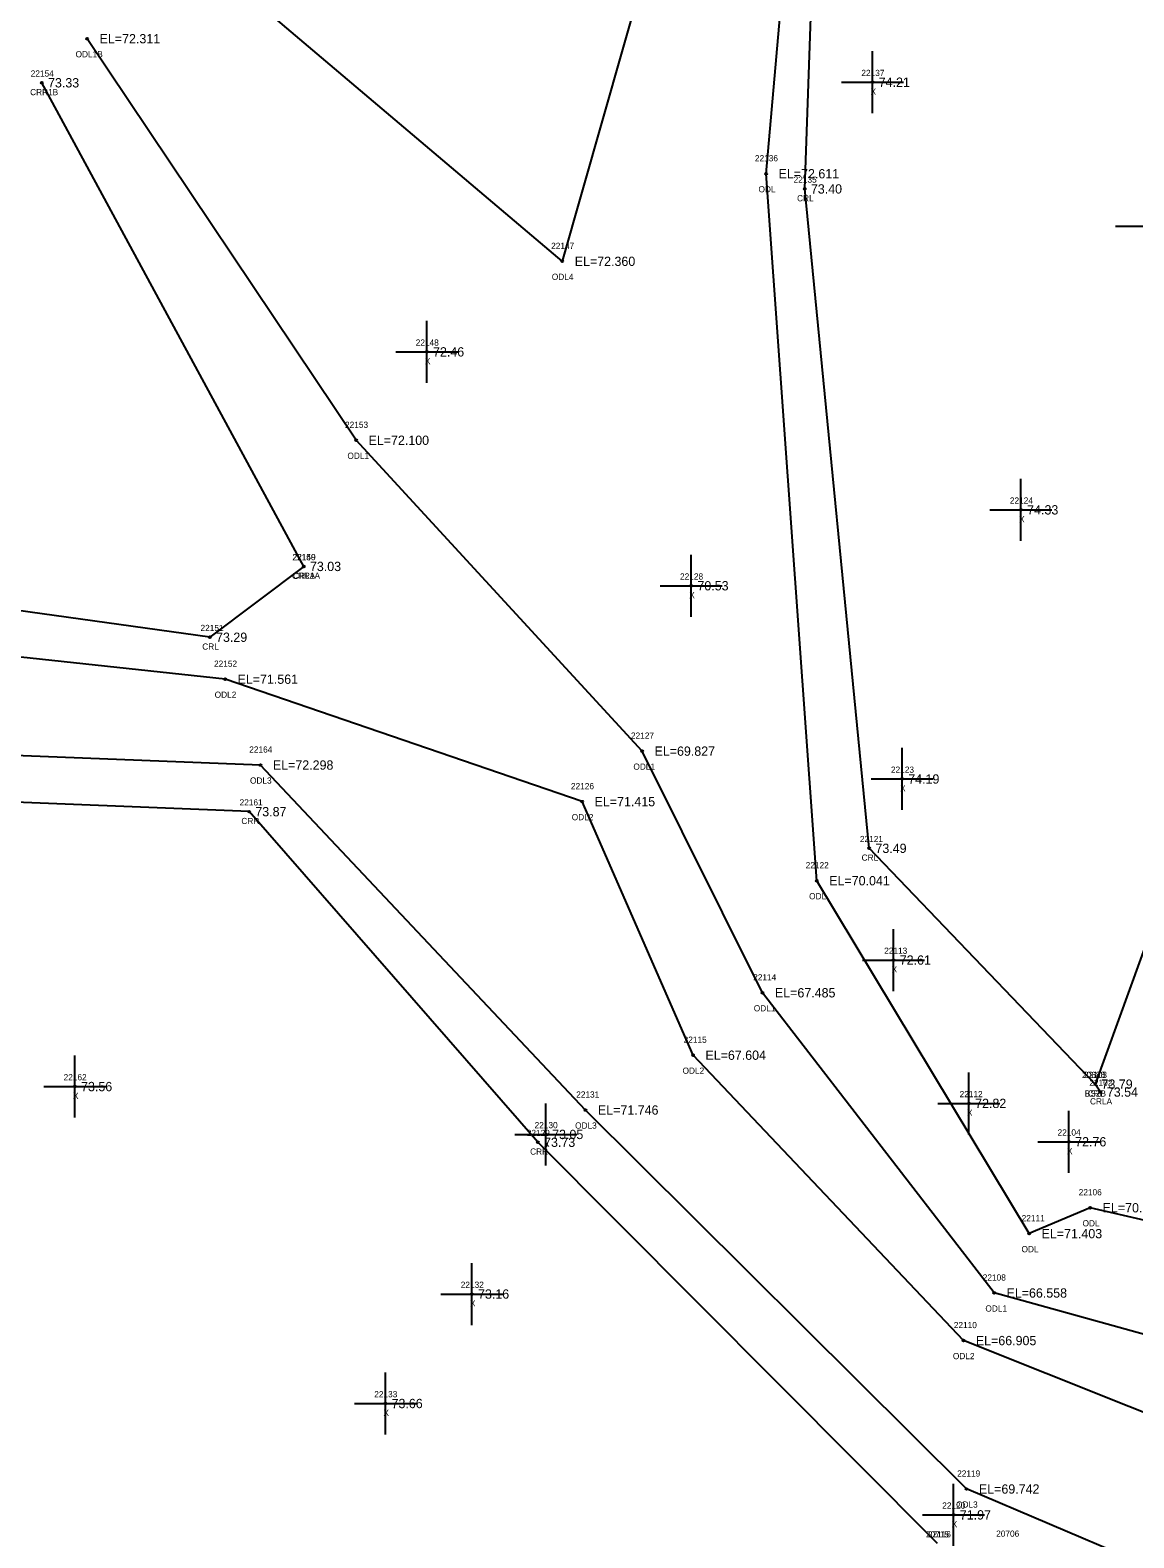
# Model space of a CAD drawing. Extents: x 2140110 to 2141565, y 506241 to 510327.
# Drawn here: x 2140519.7 to 2140697.7, y 508335.5 to 508578.6 of the extents above; entities that cross this region are included whole.
import ezdxf

# ---------------------------------------------------------------- set-up
doc = ezdxf.new("R2010")
doc.units = 0
for name, color, linetype in [('RD_DTM_BkLn2', 7, 'Continuous'), ('RD_DTM_BkLn_txCode', 7, 'Continuous'), ('RD_EX_H2O', 7, 'Continuous'), ('RD_EX_H2O_txCode', 7, 'Continuous'), ('RD_EX_Misc', 7, 'Continuous'), ('RD_EX_Misc_txCode', 7, 'Continuous'), ('RD_EX_Road_txCode', 7, 'Continuous'), ('RD_EX_TX_H2O_ELEV', 7, 'Continuous'), ('RD_EX_TX_Misc_ELEV', 7, 'Continuous'), ('RD_SMD_Locator', 7, 'Continuous')]:
    doc.layers.add(name, color=color, linetype=linetype)

msp = doc.modelspace()

# ---------------------------------------------------------------- linework, layer by layer
at = {"layer": 'RD_DTM_BkLn2'}
msp.add_lwpolyline([(2140933.17, 509059.34), (2140899.55, 508966.27), (2140862.01, 508865.36), (2140827.25, 508770.26), (2140789.14, 508668.2), (2140752.1, 508574.12), (2140728.15, 508510.71), (2140713.66, 508469.65), (2140691.53, 508408.63)], dxfattribs=at)
at = {"layer": 'RD_EX_H2O'}
msp.add_line((2140563.87, 508492.1), (2140521.63, 508570.07), dxfattribs=at)
for points in [[(2140731.12, 508379.38), (2140690.71, 508388.7), (2140680.87, 508384.53), (2140646.62, 508441.43), (2140638.45, 508555.41), (2140644.51, 508624.42), (2140598.18, 508668.32)], [(2140692.39, 508407.36), (2140691.53, 508408.63), (2140655.07, 508446.65), (2140644.66, 508552.96), (2140647.23, 508625.31), (2140600.11, 508668.87)], [(2140579.39, 508634.97), (2140625.02, 508609.64), (2140605.57, 508541.29), (2140545.38, 508592.28)], [(2140728.33, 508360.27), (2140675.21, 508374.96), (2140637.86, 508423.36), (2140618.44, 508462.32), (2140572.32, 508512.44), (2140528.95, 508577.18)], [(2140563.87, 508492.1), (2140548.73, 508480.68), (2140450.57, 508494.36), (2140392.48, 508505.39), (2140313.19, 508474.64), (2140226.29, 508430.33)], [(2140723.61, 508346.04), (2140670.26, 508367.29), (2140626.65, 508413.3), (2140608.78, 508454.18), (2140551.19, 508473.92), (2140449.81, 508484.81), (2140391.74, 508490.96), (2140313.16, 508466.4), (2140228.88, 508423.28)], [(2140719.99, 508318.3), (2140710.89, 508326.31), (2140670.76, 508343.36), (2140609.32, 508404.46), (2140556.89, 508460.08), (2140448.82, 508464.32), (2140396.19, 508466.05), (2140326.89, 508440.8), (2140236.16, 508393.77)], [(2140666.06, 508334.55), (2140601.63, 508399.26), (2140555.06, 508452.56), (2140445.76, 508456.93), (2140394.38, 508460.34), (2140330.91, 508434.11), (2140238.02, 508387.64)]]:
    msp.add_lwpolyline(points, dxfattribs=at)
at = {"layer": 'RD_EX_Misc'}
for p, q in [((2140655.6, 508565.16), (2140655.6, 508575.16)), ((2140650.6, 508570.16), (2140660.6, 508570.16)), ((2140694.76, 508546.95), (2140704.76, 508546.95)), ((2140583.72, 508521.69), (2140583.72, 508531.69)), ((2140578.72, 508526.69), (2140588.72, 508526.69)), ((2140679.54, 508496.22), (2140679.54, 508506.22)), ((2140674.54, 508501.22), (2140684.54, 508501.22)), ((2140626.36, 508483.98), (2140626.36, 508493.98)), ((2140621.36, 508488.98), (2140631.36, 508488.98)), ((2140660.36, 508452.83), (2140660.36, 508462.83)), ((2140655.36, 508457.83), (2140665.36, 508457.83)), ((2140658.99, 508423.64), (2140658.99, 508433.64)), ((2140653.99, 508428.64), (2140663.99, 508428.64)), ((2140526.96, 508403.24), (2140526.96, 508413.24)), ((2140671.15, 508400.53), (2140671.15, 508410.53)), ((2140521.96, 508408.24), (2140531.96, 508408.24)), ((2140602.93, 508395.52), (2140602.93, 508405.52)), ((2140666.15, 508405.53), (2140676.15, 508405.53)), ((2140687.28, 508394.34), (2140687.28, 508404.34)), ((2140597.93, 508400.52), (2140607.93, 508400.52)), ((2140682.28, 508399.34), (2140692.28, 508399.34)), ((2140590.98, 508369.79), (2140590.98, 508379.79)), ((2140585.98, 508374.79), (2140595.98, 508374.79)), ((2140577.03, 508352.14), (2140577.03, 508362.14)), ((2140572.03, 508357.14), (2140582.03, 508357.14)), ((2140668.68, 508334.19), (2140668.68, 508344.19)), ((2140663.68, 508339.19), (2140673.68, 508339.19))]:
    msp.add_line(p, q, dxfattribs=at)
at = {"layer": 'RD_SMD_Locator'}
for centre in [(2140528.95, 508577.18), (2140521.63, 508570.07), (2140655.6, 508570.16), (2140638.45, 508555.41), (2140644.66, 508552.96), (2140605.57, 508541.29), (2140583.72, 508526.69), (2140572.32, 508512.44), (2140679.54, 508501.22), (2140563.87, 508492.1), (2140563.87, 508492.1), (2140626.36, 508488.98), (2140548.73, 508480.68), (2140551.19, 508473.92), (2140618.44, 508462.32), (2140556.89, 508460.08), (2140660.36, 508457.83), (2140608.78, 508454.18), (2140555.06, 508452.56), (2140655.07, 508446.65), (2140646.62, 508441.43), (2140658.99, 508428.64), (2140637.86, 508423.36), (2140626.65, 508413.3), (2140526.96, 508408.24), (2140691.53, 508408.63), (2140691.53, 508408.63), (2140671.15, 508405.53), (2140692.39, 508407.36), (2140609.32, 508404.46), (2140602.93, 508400.52), (2140601.63, 508399.26), (2140687.28, 508399.34), (2140690.71, 508388.7), (2140680.87, 508384.53), (2140590.98, 508374.79), (2140675.21, 508374.96), (2140670.26, 508367.29), (2140577.03, 508357.14), (2140670.76, 508343.36), (2140668.68, 508339.19)]:
    msp.add_circle(centre, 0.15, dxfattribs=at)

# ---------------------------------------------------------------- texts
at = {"layer": 'RD_DTM_BkLn_txCode'}
for s, p in [('20688', (2140689.39, 508409.63)), ('BS2B', (2140689.83, 508406.63)), ('20715', (2140664.22, 508335.55))]:
    msp.add_text(s, height=1, dxfattribs=at).set_placement(p)
at = {"layer": 'RD_EX_H2O_txCode'}
for s, p in [('ODL1B', (2140527.07, 508574.18)), ('22154', (2140519.84, 508571.07)), ('CRR1B', (2140519.74, 508568.07)), ('22136', (2140636.63, 508557.41)), ('22135', (2140642.87, 508553.96)), ('ODL', (2140637.21, 508552.41)), ('CRL', (2140643.43, 508550.96)), ('22147', (2140603.77, 508543.29)), ('ODL4', (2140603.88, 508538.29)), ('22153', (2140570.53, 508514.44)), ('ODL1', (2140570.91, 508509.44)), ('22150', (2140562.04, 508493.1)), ('22149', (2140562.08, 508493.1)), ('CRR1A', (2140561.97, 508490.1)), ('CRLA', (2140562.15, 508490.1)), ('22151', (2140547.22, 508481.68)), ('CRL', (2140547.5, 508478.68)), ('22152', (2140549.4, 508475.92)), ('ODL2', (2140549.5, 508470.92)), ('22127', (2140616.64, 508464.32)), ('22164', (2140555.08, 508462.08)), ('ODL1', (2140617.03, 508459.32)), ('ODL3', (2140555.2, 508457.08)), ('22126', (2140606.96, 508456.18)), ('22161', (2140553.52, 508453.56)), ('CRR', (2140553.81, 508450.56)), ('ODL2', (2140607.09, 508451.18)), ('22121', (2140653.56, 508447.65)), ('22122', (2140644.82, 508443.43)), ('CRL', (2140653.84, 508444.65)), ('ODL', (2140645.37, 508438.43)), ('22114', (2140636.35, 508425.36)), ('ODL1', (2140636.45, 508420.36)), ('22115', (2140625.14, 508415.3)), ('ODL2', (2140624.96, 508410.3)), ('22103', (2140689.69, 508409.63)), ('22102', (2140690.56, 508408.36)), ('22131', (2140607.81, 508406.46)), ('CRL', (2140690.3, 508406.63)), ('CRLA', (2140690.67, 508405.36)), ('22129', (2140599.84, 508400.26)), ('ODL3', (2140607.63, 508401.46)), ('CRR', (2140600.38, 508397.26)), ('22106', (2140688.85, 508390.7)), ('22111', (2140679.65, 508386.53)), ('ODL', (2140689.47, 508385.7)), ('ODL', (2140679.63, 508381.53)), ('22108', (2140673.38, 508376.96)), ('ODL1', (2140673.8, 508371.96)), ('22110', (2140668.71, 508369.29)), ('ODL2', (2140668.56, 508364.29)), ('22119', (2140669.25, 508345.36)), ('ODL3', (2140669.07, 508340.36)), ('22116', (2140664.52, 508335.55))]:
    msp.add_text(s, height=1, dxfattribs=at).set_placement(p)
at = {"layer": 'RD_EX_Misc_txCode'}
for s, p in [('22137', (2140653.8, 508571.16)), ('X', (2140655.28, 508568.16)), ('22148', (2140581.93, 508527.69)), ('X', (2140583.41, 508524.69)), ('22124', (2140677.75, 508502.22)), ('X', (2140679.23, 508499.22)), ('22128', (2140624.56, 508489.98)), ('X', (2140626.04, 508486.98)), ('22123', (2140658.57, 508458.83)), ('X', (2140660.05, 508455.83)), ('22113', (2140657.48, 508429.64)), ('X', (2140658.68, 508426.64)), ('22162', (2140525.14, 508409.24)), ('X', (2140526.64, 508406.24)), ('22112', (2140669.64, 508406.53)), ('X', (2140670.83, 508403.53)), ('22130', (2140601.1, 508401.52)), ('22104', (2140685.44, 508400.34)), ('X', (2140602.62, 508398.52)), ('X', (2140686.96, 508397.34)), ('22132', (2140589.19, 508375.79)), ('X', (2140590.67, 508372.79)), ('22133', (2140575.24, 508358.14)), ('X', (2140576.72, 508355.14)), ('22120', (2140666.84, 508340.19)), ('X', (2140668.36, 508337.19))]:
    msp.add_text(s, height=1, dxfattribs=at).set_placement(p)
at = {"layer": 'RD_EX_Road_txCode'}
msp.add_text('20706', height=1, dxfattribs=at).set_placement((2140675.54, 508335.66))
at = {"layer": 'RD_EX_TX_H2O_ELEV'}
for s, p in [('EL=72.311', (2140530.95, 508576.43)), ('73.33', (2140522.63, 508569.32)), ('EL=72.611', (2140640.45, 508554.66)), ('73.40', (2140645.66, 508552.21)), ('EL=72.360', (2140607.57, 508540.54)), ('EL=72.100', (2140574.32, 508511.69)), ('73.03', (2140564.87, 508491.35)), ('73.03', (2140564.87, 508491.35)), ('73.29', (2140549.73, 508479.93)), ('EL=71.561', (2140553.19, 508473.17)), ('EL=69.827', (2140620.44, 508461.57)), ('EL=72.298', (2140558.89, 508459.33)), ('EL=71.415', (2140610.78, 508453.43)), ('73.87', (2140556.06, 508451.81)), ('73.49', (2140656.07, 508445.9)), ('EL=70.041', (2140648.62, 508440.68)), ('EL=67.485', (2140639.86, 508422.61)), ('EL=67.604', (2140628.65, 508412.55)), ('73.79', (2140692.53, 508407.88)), ('73.54', (2140693.39, 508406.61)), ('EL=71.746', (2140611.32, 508403.71)), ('73.73', (2140602.63, 508398.51)), ('EL=70.710', (2140692.71, 508387.95)), ('EL=71.403', (2140682.87, 508383.78)), ('EL=66.558', (2140677.21, 508374.21)), ('EL=66.905', (2140672.26, 508366.54)), ('EL=69.742', (2140672.76, 508342.61))]:
    msp.add_text(s, height=1.5, dxfattribs=at).set_placement(p)
at = {"layer": 'RD_EX_TX_Misc_ELEV'}
for s, p in [('74.21', (2140656.6, 508569.41)), ('72.46', (2140584.72, 508525.94)), ('74.33', (2140680.54, 508500.47)), ('70.53', (2140627.36, 508488.23)), ('74.19', (2140661.36, 508457.08)), ('72.61', (2140659.99, 508427.89)), ('73.56', (2140527.96, 508407.49)), ('73.79', (2140692.53, 508407.88)), ('72.82', (2140672.15, 508404.78)), ('73.05', (2140603.93, 508399.77)), ('72.76', (2140688.28, 508398.59)), ('73.16', (2140591.98, 508374.04)), ('73.66', (2140578.03, 508356.39)), ('71.97', (2140669.68, 508338.44))]:
    msp.add_text(s, height=1.5, dxfattribs=at).set_placement(p)

doc.saveas('drawing.dxf')
